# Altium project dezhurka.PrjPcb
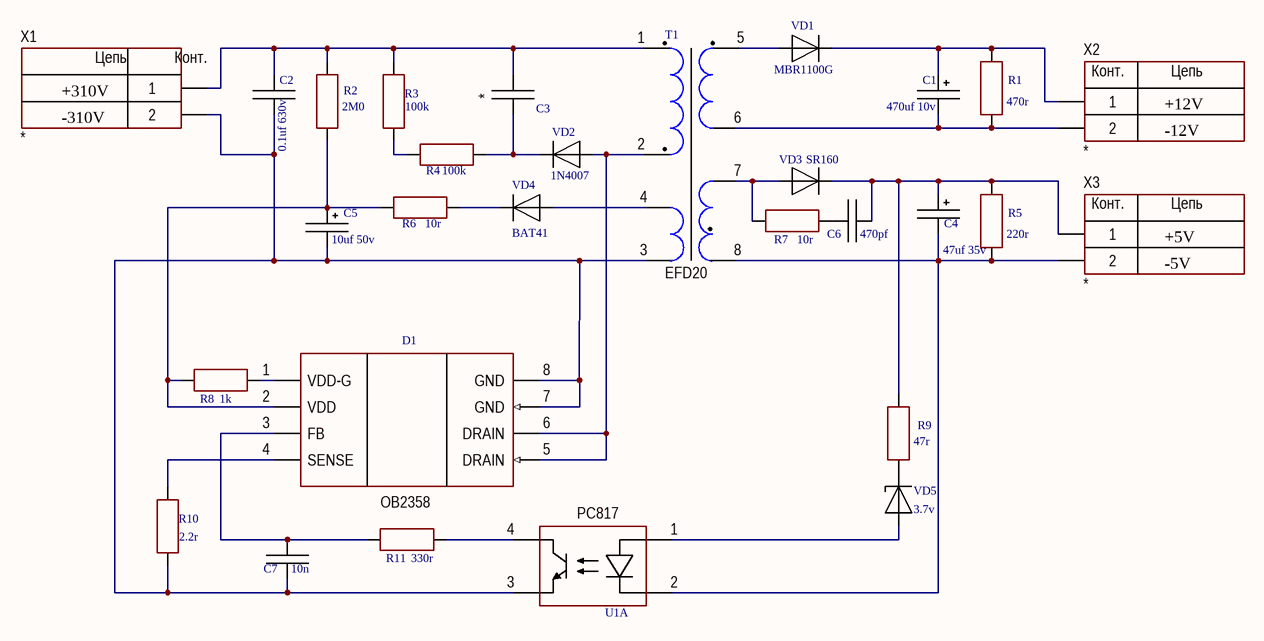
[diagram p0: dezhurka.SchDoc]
1 sheet, 29 parts. Net scope: global (net labels, ports and power ports of the same name join across sheets).
Board file: dezhurka_small_holes.PcbDoc

## Sheet dezhurka.SchDoc
size 297 x 209 mm; Address1: Address1; Address2: Address2; Address3: Address3; Address4: Address4; DocumentNumber: АБВГ.123456.001 Э3; SheetNumber: 1; Scale: 1:1; DocumentType: Схема электрическая принципиальная; FirstReferrence: АБВГ.123456.001

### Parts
C1  470uf 10v  [D6.3C2.5H11]
C2  0.1uf 630v  [MKP 10x4 h9 R7.62]
C3  *  [MKP 10x4 h9 R7.62]
C4  47uf 35v  [D6.3C2.5H11]
C5  10uf 50v  [D5C2H11]
C6  470pf  [Cap-Disk-D5.5-R5.08]
C7  10n  [Cap-Disk-D5.5-R2.54]
D1  OB2358  [8-DIP]
R1  470r  [R0.125-200]
R2  2M0  [R0.125-200]
R3  100k  [R0.125-200]
R4  100k  [R0.125-200]
R5  220r  [R0.125-200]
R6  10r  [R0.125-200]
R7  10r  [R0.125-200]
R8  1k  [R0.125-200]
R9  47r  [R0.125-200]
R10  2.2r  [R0.125-200]
R11  330r  [R0.125-200]
T1  EFD20  [TRANS: EFD20_8Pin]
U1  PC817  [4-DIP]  (parts A,B of 2)
VD1  MBR1100G  [DO-41 Ver-100]
VD2  1N4007  [DO-41 Ver-150]
VD3  SR160  [DO-41 Ver-150]
VD4  BAT41  [DO-41 Ver-200R]
VD5  3.7v  [DO35]
X1  *  [CON: PLS-2]
X2  *  [CON: PLS-2]
X3  *  [CON: PLS-2]

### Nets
NetC1_1: C1.1 R1.2 VD1.2 X2.1
NetC1_2: C1.2 R1.1 T1.6 X2.2
NetC2_1: C2.1 C3.1 R2.1 R3.1 T1.1 X1.1
NetC2_2: C2.2 C5.2 C7.2 D1.7(GND) D1.8(GND) R10.1 T1.3 U1.3(E) X1.2
NetC3_2: C3.2 R4.1 VD2.2
NetC4_1: C4.1 C6.2 R5.2 R9.2 VD3.2 X3.1
NetC4_2: C4.2 R5.1 T1.8 U1.2(C) X3.2
NetC5_1: C5.1 D1.2(VDD) R2.2 R6.2 R8.2
NetC6_1: C6.1 R7.2
NetC7_1: C7.1 D1.3(FB) R11.2
NetD1_1: D1.1(VDD-G) R8.1
NetD1_4: D1.4(SENSE) R10.2
NetD1_5: D1.5(DRAIN) D1.6(DRAIN) T1.2 VD2.1
NetR3_2: R3.2 R4.2
NetR6_1: R6.1 VD4.2
NetR7_1: R7.1 T1.7 VD3.1
NetR9_1: R9.1 VD5.2(C)
NetR11_1: R11.1 U1.4(C)
NetT1_4: T1.4 VD4.1
NetT1_5: T1.5 VD1.1
NetU1_1: U1.1(A) VD5.1(A)

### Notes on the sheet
- +310V
- +12V
- -310V
- -12V
- +5V
- -5V

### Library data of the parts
C1 C4 C5 = AlumCap
C2 C3 C6 C7 = Capacitor
D1 = OB2358: Sensor; Manufacturer: Texas Instruments; Model: MC34063ADR
R1-R11 = Resistor
T1 = EFD20_2_OUTPUT: Sensor; Manufacturer: Tamura
U1 = Optoisolator: Manufacturer: Lite-On Inc.; Model: LTV-817S
VD1-VD4 = Diod
VD5 = Diod Zener
X1-X3 = 2-Connector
